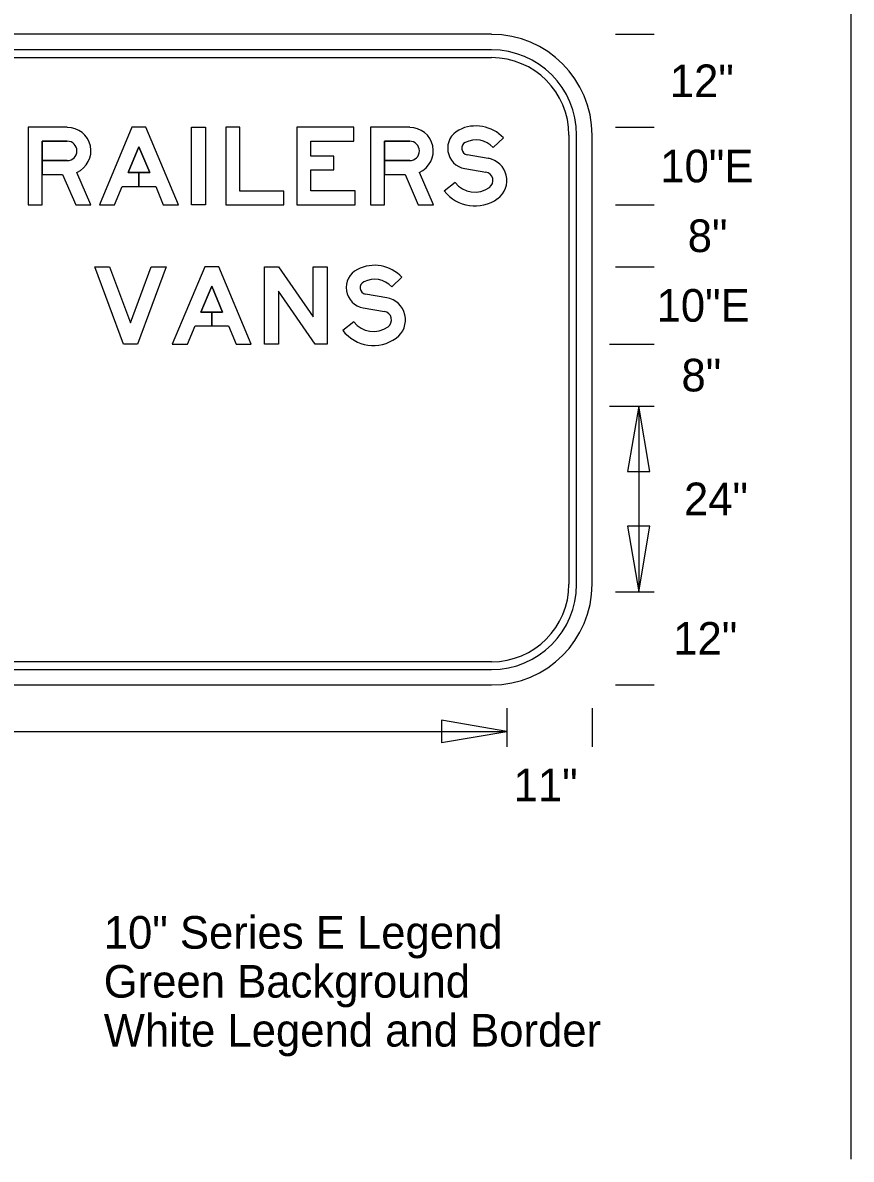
# Model space of a CAD drawing. Extents: x 0 to 770, y 0 to 495.
# Drawn here: x 488.9 to 577.8, y 0 to 121.9 of the extents above; entities that cross this region are included whole.
import ezdxf

# ---------------------------------------------------------------- set-up
doc = ezdxf.new("R2010")
doc.units = 0
for name, color, linetype in [('Dimension', 7, 'Continuous'), ('GSBWFill', 7, 'Continuous'), ('GSColorFill', 7, 'Continuous'), ('GSDims', 7, 'Continuous'), ('GSOutline', 7, 'Continuous'), ('SheetLines_dp', 7, 'Continuous'), ('TextStructures', 7, 'Continuous')]:
    doc.layers.add(name, color=color, linetype=linetype)

msp = doc.modelspace()

# ---------------------------------------------------------------- linework, layer by layer
at = {"layer": 'Dimension'}
for points in [[(555, 80.79), (553.81, 73.78), (556.18, 73.78)], [(555, 60.88), (556.18, 67.9), (553.81, 67.9)], [(540.87, 45.9), (533.85, 47.09), (533.85, 44.71)]]:
    msp.add_lwpolyline(points, close=True, dxfattribs=at)
at = {"layer": 'GSBWFill'}
for p, q in [((539.21, 120.68), (416.24, 120.68)), ((539.21, 119.01), (416.24, 119.01)), ((416.24, 118.18), (539.21, 118.18)), ((547.52, 109.87), (547.52, 61.68)), ((548.35, 61.68), (548.35, 109.87)), ((550.01, 61.68), (550.01, 109.87)), ((539.4, 108.54), (540.5, 109.56)), ((538.86, 107.37), (536.6, 107.75)), ((536.35, 106.28), (538.61, 105.9)), ((535.33, 104.78), (534.14, 103.87)), ((528.52, 93.59), (529.61, 94.61)), ((527.98, 92.42), (525.71, 92.8)), ((525.47, 91.32), (527.73, 90.94)), ((524.44, 89.83), (523.26, 88.92)), ((539.21, 53.38), (416.25, 53.38)), ((416.25, 52.54), (539.21, 52.54)), ((416.24, 50.88), (539.21, 50.88))]:
    msp.add_line(p, q, dxfattribs=at)
for points in [[(493.72, 110.71), (489.52, 110.71), (489.52, 102.4), (491.02, 102.4), (491.02, 109.21), (493.72, 109.21)], [(530.44, 110.71), (526.25, 110.71), (526.25, 102.4), (527.74, 102.4), (527.74, 109.21), (530.44, 109.21)], [(493.72, 107.13), (491.02, 107.13), (491.02, 105.64)], [(530.44, 107.13), (527.74, 107.13), (527.74, 105.64)], [(491.02, 105.64), (493.22, 105.64), (494.62, 102.4), (496.25, 102.4), (494.75, 105.86)], [(527.74, 105.64), (529.94, 105.64), (531.35, 102.4), (532.98, 102.4), (531.48, 105.86)]]:
    msp.add_lwpolyline(points, dxfattribs=at)
for points in [[(502.57, 105.84), (501.4, 105.84), (501.4, 104.35), (503.2, 104.35), (504.02, 102.4), (505.64, 102.4), (502.15, 110.71), (500.66, 110.71), (497.17, 102.4), (498.79, 102.4), (499.61, 104.35), (501.4, 104.35), (501.4, 105.84), (500.24, 105.84), (501.4, 108.62)], [(507.05, 102.4), (507.05, 110.71), (508.55, 110.71), (508.55, 102.4)], [(516.94, 102.4), (516.94, 103.85), (512.21, 103.85), (512.21, 110.71), (510.71, 110.71), (510.71, 102.4)], [(524.59, 103.89), (519.85, 103.89), (519.85, 106.13), (522.3, 106.13), (522.3, 107.62), (519.85, 107.62), (519.85, 109.21), (524.46, 109.21), (524.46, 110.71), (518.35, 110.71), (518.35, 102.4), (524.59, 102.4)], [(501.24, 87.44), (499.74, 87.44), (496.67, 95.75), (498.26, 95.75), (500.49, 89.73), (502.72, 95.75), (504.31, 95.75)], [(510.38, 90.89), (509.22, 90.89), (509.22, 89.39), (511.01, 89.39), (511.83, 87.44), (513.45, 87.44), (509.96, 95.75), (508.47, 95.75), (504.98, 87.44), (506.6, 87.44), (507.42, 89.39), (509.21, 89.39), (509.21, 90.89), (508.05, 90.89), (509.21, 93.67)], [(521.59, 95.75), (521.59, 87.44), (520.31, 87.44), (516.36, 93.13), (516.36, 87.44), (514.86, 87.44), (514.86, 95.75), (516.37, 95.75), (520.1, 90.36), (520.1, 95.75)]]:
    msp.add_lwpolyline(points, close=True, dxfattribs=at)
for centre, radius, start, end in [((539.21, 109.87), 10.8, 0, 90), ((539.21, 109.87), 9.14, 0, 90), ((539.21, 109.87), 8.31, 0, 90), ((536.72, 108.45), 2.2, 116.9123, 260.4087), ((537.54, 106.82), 4.03, 42.8759, 116.9123), ((536.72, 108.45), 0.706, 116.9123, 260.4087), ((537.54, 106.82), 2.53, 42.8759, 116.9123), ((538.46, 105), 2.41, 306.123, 80.4087), ((538.46, 105), 0.914, 306.123, 80.4087), ((537.43, 106.41), 4.15, 217.5895, 306.123), ((537.43, 106.41), 2.66, 217.5895, 306.123), ((539.21, 61.68), 9.14, 270, 0), ((539.21, 61.68), 8.31, 270, 0), ((539.21, 61.68), 10.8, 270, 0)]:
    msp.add_arc(centre, radius, start, end, dxfattribs=at)
for centre, major_axis, start_param, end_param in [((493.72, 108.17), (0, 2.53), 3.562504, 6.283185), ((530.44, 108.17), (0, 2.53), 3.562504, 6.283185), ((493.72, 108.17), (0, 1.04), 3.141593, 6.283185), ((530.44, 108.17), (0, 1.04), 3.141593, 6.283185), ((525.83, 93.5), (0, 2.2), 0.469708, 2.974193), ((526.66, 91.87), (0, 4.03), 5.460714, 6.752893), ((525.83, 93.5), (0, 0.706), 0.469708, 2.974193), ((526.66, 91.87), (0, 2.53), 5.460714, 6.752893), ((527.58, 90.04), (0, 2.41), 3.772058, 6.115786), ((527.58, 90.04), (0, 0.914), 3.772058, 6.115786), ((526.55, 91.45), (0, 2.66), 2.226857, 3.772058), ((526.55, 91.45), (0, 4.15), 2.226857, 3.772058)]:
    msp.add_ellipse(centre, major_axis=major_axis, ratio=0.999994, start_param=start_param, end_param=end_param, dxfattribs=at)
at = {"layer": 'GSColorFill'}
for p, q in [((539.4, 108.54), (540.5, 109.56)), ((538.86, 107.37), (536.6, 107.75)), ((536.35, 106.28), (538.61, 105.9)), ((535.33, 104.78), (534.14, 103.87)), ((528.52, 93.59), (529.61, 94.61)), ((527.98, 92.42), (525.71, 92.8)), ((525.47, 91.32), (527.73, 90.94)), ((524.44, 89.83), (523.26, 88.92))]:
    msp.add_line(p, q, dxfattribs=at)
for points in [[(493.72, 110.71), (489.52, 110.71), (489.52, 102.4), (491.02, 102.4), (491.02, 109.21), (493.72, 109.21)], [(530.44, 110.71), (526.25, 110.71), (526.25, 102.4), (527.74, 102.4), (527.74, 109.21), (530.44, 109.21)], [(493.72, 107.13), (491.02, 107.13), (491.02, 105.64)], [(530.44, 107.13), (527.74, 107.13), (527.74, 105.64)], [(491.02, 105.64), (493.22, 105.64), (494.62, 102.4), (496.25, 102.4), (494.75, 105.86)], [(527.74, 105.64), (529.94, 105.64), (531.35, 102.4), (532.98, 102.4), (531.48, 105.86)]]:
    msp.add_lwpolyline(points, dxfattribs=at)
for points in [[(502.57, 105.84), (501.4, 105.84), (501.4, 104.35), (503.2, 104.35), (504.02, 102.4), (505.64, 102.4), (502.15, 110.71), (500.66, 110.71), (497.17, 102.4), (498.79, 102.4), (499.61, 104.35), (501.4, 104.35), (501.4, 105.84), (500.24, 105.84), (501.4, 108.62)], [(507.05, 102.4), (507.05, 110.71), (508.55, 110.71), (508.55, 102.4)], [(516.94, 102.4), (516.94, 103.85), (512.21, 103.85), (512.21, 110.71), (510.71, 110.71), (510.71, 102.4)], [(524.59, 103.89), (519.85, 103.89), (519.85, 106.13), (522.3, 106.13), (522.3, 107.62), (519.85, 107.62), (519.85, 109.21), (524.46, 109.21), (524.46, 110.71), (518.35, 110.71), (518.35, 102.4), (524.59, 102.4)], [(501.24, 87.44), (499.74, 87.44), (496.67, 95.75), (498.26, 95.75), (500.49, 89.73), (502.72, 95.75), (504.31, 95.75)], [(510.38, 90.89), (509.22, 90.89), (509.22, 89.39), (511.01, 89.39), (511.83, 87.44), (513.45, 87.44), (509.96, 95.75), (508.47, 95.75), (504.98, 87.44), (506.6, 87.44), (507.42, 89.39), (509.21, 89.39), (509.21, 90.89), (508.05, 90.89), (509.21, 93.67)], [(521.59, 95.75), (521.59, 87.44), (520.31, 87.44), (516.36, 93.13), (516.36, 87.44), (514.86, 87.44), (514.86, 95.75), (516.37, 95.75), (520.1, 90.36), (520.1, 95.75)]]:
    msp.add_lwpolyline(points, close=True, dxfattribs=at)
for centre, radius, start, end in [((536.72, 108.45), 2.2, 116.9123, 260.4087), ((537.54, 106.82), 4.03, 42.8759, 116.9123), ((536.72, 108.45), 0.706, 116.9123, 260.4087), ((537.54, 106.82), 2.53, 42.8759, 116.9123), ((538.46, 105), 2.41, 306.123, 80.4087), ((538.46, 105), 0.914, 306.123, 80.4087), ((537.43, 106.41), 4.15, 217.5895, 306.123), ((537.43, 106.41), 2.66, 217.5895, 306.123)]:
    msp.add_arc(centre, radius, start, end, dxfattribs=at)
for centre, major_axis, start_param, end_param in [((493.72, 108.17), (0, 2.53), 3.562504, 6.283185), ((530.44, 108.17), (0, 2.53), 3.562504, 6.283185), ((493.72, 108.17), (0, 1.04), 3.141593, 6.283185), ((530.44, 108.17), (0, 1.04), 3.141593, 6.283185), ((525.83, 93.5), (0, 2.2), 0.469708, 2.974193), ((526.66, 91.87), (0, 4.03), 5.460714, 6.752893), ((525.83, 93.5), (0, 0.706), 0.469708, 2.974193), ((526.66, 91.87), (0, 2.53), 5.460714, 6.752893), ((527.58, 90.04), (0, 2.41), 3.772058, 6.115786), ((527.58, 90.04), (0, 0.914), 3.772058, 6.115786), ((526.55, 91.45), (0, 2.66), 2.226857, 3.772058), ((526.55, 91.45), (0, 4.15), 2.226857, 3.772058)]:
    msp.add_ellipse(centre, major_axis=major_axis, ratio=0.999994, start_param=start_param, end_param=end_param, dxfattribs=at)
at = {"layer": 'GSDims'}
for p, q in [((552.5, 120.68), (556.66, 120.68)), ((552.5, 110.71), (556.66, 110.71)), ((552.5, 110.71), (556.66, 110.71)), ((552.5, 102.4), (556.66, 102.4)), ((552.5, 102.4), (556.66, 102.4)), ((552.5, 95.75), (556.66, 95.75)), ((552.5, 95.75), (556.66, 95.75)), ((551.88, 87.44), (555, 87.44)), ((552.5, 87.44), (556.66, 87.44)), ((552.5, 87.44), (556.66, 87.44)), ((551.88, 80.79), (555, 80.79)), ((552.5, 80.79), (556.66, 80.79)), ((552.5, 80.79), (556.66, 80.79)), ((555, 80.79), (555, 60.88)), ((552.5, 60.88), (556.66, 60.88)), ((552.5, 60.88), (556.66, 60.88)), ((552.5, 50.88), (556.66, 50.88)), ((540.87, 48.39), (540.87, 44.24)), ((540.87, 48.39), (540.87, 44.24)), ((550.01, 48.39), (550.01, 44.24)), ((414.58, 45.9), (540.87, 45.9))]:
    msp.add_line(p, q, dxfattribs=at)
at = {"layer": 'GSOutline'}
for p, q in [((539.4, 108.54), (540.5, 109.56)), ((538.86, 107.37), (536.6, 107.75)), ((491.02, 107.13), (493.72, 107.13)), ((527.74, 107.13), (530.44, 107.13)), ((536.35, 106.28), (538.61, 105.9)), ((535.33, 104.78), (534.14, 103.87)), ((528.52, 93.59), (529.61, 94.61)), ((527.98, 92.42), (525.71, 92.8)), ((525.47, 91.32), (527.73, 90.94)), ((524.44, 89.83), (523.26, 88.92))]:
    msp.add_line(p, q, dxfattribs=at)
for points in [[(493.72, 110.71), (489.52, 110.71), (489.52, 102.4), (491.02, 102.4), (491.02, 105.64), (493.22, 105.64)], [(530.44, 110.71), (526.25, 110.71), (526.25, 102.4), (527.74, 102.4), (527.74, 105.64), (529.94, 105.64)], [(493.72, 109.21), (491.02, 109.21), (491.02, 107.13)], [(530.44, 109.21), (527.74, 109.21), (527.74, 107.13)], [(493.22, 105.64), (494.62, 102.4), (496.25, 102.4), (494.75, 105.86)], [(529.94, 105.64), (531.35, 102.4), (532.98, 102.4), (531.48, 105.86)]]:
    msp.add_lwpolyline(points, dxfattribs=at)
for points in [[(499.61, 104.35), (503.2, 104.35), (504.02, 102.4), (505.64, 102.4), (502.15, 110.71), (500.66, 110.71), (497.17, 102.4), (498.79, 102.4)], [(507.05, 102.4), (507.05, 110.71), (508.55, 110.71), (508.55, 102.4)], [(516.94, 102.4), (516.94, 103.85), (512.21, 103.85), (512.21, 110.71), (510.71, 110.71), (510.71, 102.4)], [(524.59, 103.89), (519.85, 103.89), (519.85, 106.13), (522.3, 106.13), (522.3, 107.62), (519.85, 107.62), (519.85, 109.21), (524.46, 109.21), (524.46, 110.71), (518.35, 110.71), (518.35, 102.4), (524.59, 102.4)], [(502.57, 105.84), (501.4, 108.62), (500.24, 105.84)], [(501.24, 87.44), (499.74, 87.44), (496.67, 95.75), (498.26, 95.75), (500.49, 89.73), (502.72, 95.75), (504.31, 95.75)], [(507.42, 89.39), (511.01, 89.39), (511.83, 87.44), (513.45, 87.44), (509.96, 95.75), (508.47, 95.75), (504.98, 87.44), (506.6, 87.44)], [(521.59, 95.75), (521.59, 87.44), (520.31, 87.44), (516.36, 93.13), (516.36, 87.44), (514.86, 87.44), (514.86, 95.75), (516.37, 95.75), (520.1, 90.36), (520.1, 95.75)], [(510.38, 90.89), (509.21, 93.67), (508.05, 90.89)]]:
    msp.add_lwpolyline(points, close=True, dxfattribs=at)
for centre, radius, start, end in [((536.72, 108.45), 2.2, 116.9123, 260.4087), ((537.54, 106.82), 4.03, 42.8759, 116.9123), ((536.72, 108.45), 0.706, 116.9123, 260.4087), ((537.54, 106.82), 2.53, 42.8759, 116.9123), ((538.46, 105), 2.41, 306.123, 80.4087), ((538.46, 105), 0.914, 306.123, 80.4087), ((537.43, 106.41), 4.15, 217.5895, 306.123), ((537.43, 106.41), 2.66, 217.5895, 306.123)]:
    msp.add_arc(centre, radius, start, end, dxfattribs=at)
for centre, major_axis, start_param, end_param in [((493.72, 108.17), (0, 2.53), 3.562504, 6.283185), ((530.44, 108.17), (0, 2.53), 3.562504, 6.283185), ((493.72, 108.17), (0, 1.04), 3.141593, 6.283185), ((530.44, 108.17), (0, 1.04), 3.141593, 6.283185), ((525.83, 93.5), (0, 2.2), 0.469708, 2.974193), ((526.66, 91.87), (0, 4.03), 5.460714, 6.752893), ((525.83, 93.5), (0, 0.706), 0.469708, 2.974193), ((526.66, 91.87), (0, 2.53), 5.460714, 6.752893), ((527.58, 90.04), (0, 2.41), 3.772058, 6.115786), ((527.58, 90.04), (0, 0.914), 3.772058, 6.115786), ((526.55, 91.45), (0, 2.66), 2.226857, 3.772058), ((526.55, 91.45), (0, 4.15), 2.226857, 3.772058)]:
    msp.add_ellipse(centre, major_axis=major_axis, ratio=0.999994, start_param=start_param, end_param=end_param, dxfattribs=at)
at = {"layer": 'SheetLines_dp'}
msp.add_line((577.8, 0), (577.8, 495), dxfattribs=at)

# ---------------------------------------------------------------- texts
at = {"layer": 'TextStructures'}
for s, p in [('12"', (558.34, 113.94)), ('10"E', (557.32, 104.8)), ('8"', (560.26, 97.32)), ('10"E', (556.92, 89.85)), ('8"', (559.59, 82.37)), ('24"', (559.86, 69.09)), ('12"', (558.71, 54.13)), ('11"', (541.59, 38.4)), ('10" Series E Legend', (497.63, 22.59)), ('Green Background', (497.63, 17.34)), ('White Legend and Border', (497.63, 12.09))]:
    msp.add_text(s, height=3.5, dxfattribs=at).set_placement(p)

doc.saveas('drawing.dxf')
